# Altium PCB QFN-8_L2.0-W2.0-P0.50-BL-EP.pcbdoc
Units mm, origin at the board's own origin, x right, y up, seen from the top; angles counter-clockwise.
Board outline 15.2 x 15.4 mm, 2 copper layers (Top Layer, Bottom Layer), stack 0 mm thick; 1 components, 0 nets, 9 pads, 0 vias.
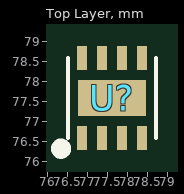
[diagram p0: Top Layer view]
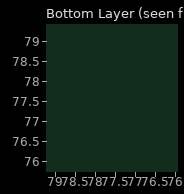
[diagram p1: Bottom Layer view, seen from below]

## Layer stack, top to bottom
Top Layer: signal copper (thickness not stored)
Bottom Layer: signal copper (thickness not stored)

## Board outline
85.047,69.85 69.85,69.85 69.85,85.247 85.047,85.247

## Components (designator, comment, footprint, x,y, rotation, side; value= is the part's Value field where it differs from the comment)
U? "" QFN-8_L2.0-W2.0-P0.50-BL-EP 77.597,77.597 r0 top

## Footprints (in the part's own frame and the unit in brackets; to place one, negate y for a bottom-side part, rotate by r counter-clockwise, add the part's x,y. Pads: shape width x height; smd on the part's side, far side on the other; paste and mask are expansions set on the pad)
QFN-8_L2.0-W2.0-P0.50-BL-EP [mm]
  rect 0.25x0.6 smd: 1(-0.75,-1) 2(-0.25,-1) 3(0.25,-1) 4(0.75,-1) 5(0.75,1) 6(0.25,1) 7(-0.25,1) 8(-0.75,1)
  rect 1.7x0.9 smd: 9(0,-0.001)
  silkscreen extent -1.4,-1.4 1.1,1

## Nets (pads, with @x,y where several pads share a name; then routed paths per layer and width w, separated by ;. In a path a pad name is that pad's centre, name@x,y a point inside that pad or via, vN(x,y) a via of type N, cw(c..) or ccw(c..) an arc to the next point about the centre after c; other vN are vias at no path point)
pads on no net: U?.1 U?.2 U?.3 U?.4 U?.5 U?.6 U?.7 U?.8 U?.9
